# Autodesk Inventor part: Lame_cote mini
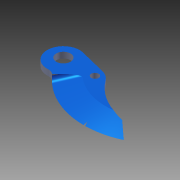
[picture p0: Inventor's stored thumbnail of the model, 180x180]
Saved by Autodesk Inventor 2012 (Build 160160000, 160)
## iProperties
Created: 2014-12
Part Number: Lame_cote mini
Material: Default
Document SubType Name: Modeling
Designer: Bruno
Density: 1 g/cm^3
Mass: 4.15622 g
Surface Area: 35.6042 cm^2
Volume: 4.15622 cm^3
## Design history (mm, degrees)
node "Lame_cote mini1"
sketch "Esquisse1"
  geometry: L1 (0, -56.284)-(0, -50.697); L2 (0, -50.697)-(-2.255, -56.284); L3 (-2.255, -56.284)-(0, -56.284); L4 (-8.075, -56.284)-(-7.105, -50.673); L5 (-7.105, -50.673)-(-9.859, -55.198); L6 (-9.859, -55.198)-(-8.075, -56.284)
  constraints: 12 end point, 2 perpendicular, 1 vertical
extrude "Extrusion1" cut sketch "Esquisse1" distance "d0" = 10; taper "d1" = 0 deg
node "Lame_cote mini"
node "Base1"
